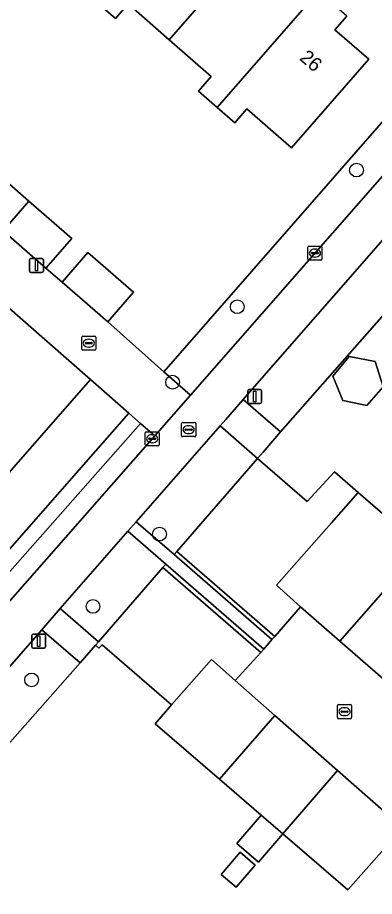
# Model space of a CAD drawing. Extents: x 158472 to 159562, y 388525 to 389606.
# Drawn here: x 158950 to 158975.4, y 388848.4 to 388910.9 of the extents above; entities that cross this region are included whole.
import ezdxf

# ---------------------------------------------------------------- set-up
doc = ezdxf.new("R2010")
doc.units = 0
for name, color, linetype in [('IMGEO_Berm_groen', 7, 'Continuous'), ('IMGEO_Boom', 7, 'Continuous'), ('IMGEO_Erf', 7, 'Continuous'), ('IMGEO_Fietspad_gesloten', 7, 'Continuous'), ('IMGEO_Groenvoorziening', 7, 'Continuous'), ('IMGEO_Kolk', 7, 'Continuous'), ('IMGEO_Lichtmast', 7, 'Continuous'), ('IMGEO_Muur', 7, 'Continuous'), ('IMGEO_Pand', 7, 'Continuous'), ('IMGEO_Pand_nummerreeks', 7, 'Continuous'), ('IMGEO_Rijbaan_lokaal_open', 7, 'Continuous'), ('IMGEO_Rioolput', 7, 'Continuous'), ('IMGEO_Voetpad_open', 7, 'Continuous')]:
    doc.layers.add(name, color=color, linetype=linetype)

msp = doc.modelspace()

# ---------------------------------------------------------------- linework, layer by layer
at = {"layer": 'IMGEO_Berm_groen'}
for points in [[(158986.075, 388905.713), (158985.406, 388905.499), (158984.817, 388905.117), (158966.103, 388883.752), (158968.762, 388881.439), (158988.788, 388904.188)], [(158954.488, 388865.021), (158951.767, 388867.379), (158941.937, 388856.138), (158932.045, 388844.827)], [(158932.107, 388843.92), (158934.223, 388842.084), (158954.488, 388865.021)]]:
    msp.add_lwpolyline(points, dxfattribs=at)
for points in [[(158967.11, 388879.563), (158964.456, 388881.871), (158958.484, 388875.052), (158961.177, 388872.718), (158961.375, 388872.943)], [(158960.386, 388871.802), (158960.59, 388872.036), (158957.887, 388874.378), (158953.083, 388868.884), (158955.81, 388866.522)]]:
    msp.add_lwpolyline(points, close=True, dxfattribs=at)
at = {"layer": 'IMGEO_Boom'}
for centre in [(158974.162, 388900.065), (158965.679, 388890.348), (158961.072, 388884.979), (158960.143, 388874.179), (158955.41, 388869.039), (158951.045, 388863.807)]:
    msp.add_circle(centre, 0.489, dxfattribs=at)
at = {"layer": 'IMGEO_Erf'}
for points in [[(158916.349, 388912.847), (158912.713, 388908.701), (158917.24, 388904.733), (158921.825, 388900.714), (158924.012, 388898.797), (158926.241, 388896.842), (158922.576, 388892.663), (158927.12, 388888.678), (158929.463, 388886.623), (158930.515, 388887.823), (158932.528, 388887.999), (158933.736, 388886.94), (158935.906, 388885.038), (158940.415, 388881.084), (158938.432, 388878.823), (158940.675, 388876.856), (158943.023, 388874.797), (158945.014, 388877.068), (158946.766, 388875.531), (158955.225, 388885.178), (158933.436, 388904.261), (158929.786, 388907.457), (158928.836, 388908.759), (158918.298, 388933.043)], [(158928.728, 388923.855), (158935.982, 388907.162), (158945.799, 388898.553), (158947.637, 388900.659), (158950.849, 388897.857), (158953.895, 388895.199), (158952.057, 388893.093), (158953.206, 388892.096), (158955.047, 388894.211), (158958.302, 388891.378), (158956.461, 388889.263), (158960.457, 388885.716), (158982.198, 388910.573), (158963.265, 388927.1)], [(158973.473, 388911.017), (158972.628, 388910.046), (158975.03, 388907.954), (158969.541, 388901.65), (158966.363, 388904.418), (158965.499, 388903.426), (158964.255, 388904.51), (158962.923, 388905.67), (158963.83, 388906.713), (158960.832, 388909.324), (158957.901, 388911.876), (158957, 388910.841), (158955.599, 388912.061)], [(158977.456, 388853.29), (158973.547, 388848.892), (158968.923, 388852.867), (158967.178, 388850.853), (158965.638, 388852.177), (158967.382, 388854.192), (158964.404, 388856.752), (158959.822, 388860.691), (158960.987, 388862.036), (158956.052, 388866.312), (158955.835, 388866.062), (158955.593, 388866.271), (158954.488, 388865.021), (158934.223, 388842.084), (158935.951, 388840.584), (158962.949, 388817.149), (158977.95, 388834.432)]]:
    msp.add_lwpolyline(points, dxfattribs=at)
for points in [[(159014.649, 388873.584), (159009.7, 388879.13), (159009.691, 388881.445), (159000, 388891.989), (158988.788, 388904.188), (158968.762, 388881.439), (158967.507, 388880.013), (158967.11, 388879.563), (158970.648, 388876.486), (158972.587, 388878.607), (158974.289, 388877.137), (158978.812, 388873.23), (158976.909, 388871.042), (158981.434, 388867.108), (158983.016, 388868.906), (158984.505, 388867.595), (158982.931, 388865.806), (158985.959, 388863.173), (158990.479, 388859.243), (158992.082, 388857.849), (158995.085, 388855.237), (158999.05, 388855.408), (159000, 388856.515)], [(158976.064, 388884.655), (158974.887, 388883.313), (158973.195, 388883.687), (158972.474, 388885.408), (158973.645, 388886.806), (158975.487, 388886.444)], [(158961.177, 388872.718), (158968.144, 388866.68), (158968.34, 388866.907), (158961.375, 388872.943)], [(158960.386, 388871.802), (158967.351, 388865.766), (158967.554, 388866), (158960.59, 388872.036)], [(158964.528, 388849.984), (158965.878, 388851.554), (158966.948, 388850.635), (158965.598, 388849.064)]]:
    msp.add_lwpolyline(points, close=True, dxfattribs=at)
at = {"layer": 'IMGEO_Fietspad_gesloten'}
for points in [[(158982.556, 388907.1), (158962.346, 388884.059), (158959.807, 388881.165), (158941.286, 388860.117), (158939.547, 388858.13), (158926.586, 388843.327)], [(158932.045, 388844.827), (158941.937, 388856.138), (158951.767, 388867.379), (158953.083, 388868.884), (158957.887, 388874.378), (158958.484, 388875.052), (158964.456, 388881.871), (158964.852, 388882.323), (158966.103, 388883.752), (158984.817, 388905.117)]]:
    msp.add_lwpolyline(points, dxfattribs=at)
at = {"layer": 'IMGEO_Groenvoorziening'}
msp.add_lwpolyline([(158940.228, 388861.047), (158958.799, 388882.048), (158957.965, 388882.778), (158949.482, 388873.138), (158945.42, 388868.506), (158939.514, 388861.675)], close=True, dxfattribs=at)
at = {"layer": 'IMGEO_Kolk'}
for p, q in [((158970.777, 388894.66), (158971.629, 388894.66)), ((158970.702, 388893.734), (158970.702, 388894.586)), ((158970.961, 388894.154), (158970.961, 388894.166)), ((158971.399, 388894.117), (158971.001, 388894.117)), ((158971.004, 388894.203), (158971.402, 388894.203)), ((158971.19, 388894.44), (158971.215, 388894.44)), ((158971.445, 388894.166), (158971.445, 388894.154)), ((158971.703, 388894.586), (158971.703, 388893.734)), ((158971.629, 388893.66), (158970.777, 388893.66)), ((158971.213, 388893.88), (158971.188, 388893.88)), ((158954.615, 388887.328), (158954.615, 388888.18)), ((158954.69, 388888.254), (158955.542, 388888.254)), ((158954.874, 388887.748), (158954.874, 388887.76)), ((158954.917, 388887.797), (158955.315, 388887.797)), ((158955.103, 388888.034), (158955.128, 388888.034)), ((158955.358, 388887.76), (158955.358, 388887.748)), ((158955.616, 388888.18), (158955.616, 388887.328)), ((158955.542, 388887.254), (158954.69, 388887.254)), ((158955.312, 388887.711), (158954.914, 388887.711)), ((158955.126, 388887.474), (158955.101, 388887.474)), ((158959.122, 388880.532), (158959.122, 388881.384)), ((158959.197, 388881.458), (158960.049, 388881.458)), ((158959.381, 388880.952), (158959.381, 388880.964)), ((158959.819, 388880.915), (158959.421, 388880.915)), ((158959.424, 388881.001), (158959.822, 388881.001)), ((158959.61, 388881.238), (158959.635, 388881.238)), ((158959.865, 388880.964), (158959.865, 388880.952)), ((158960.123, 388881.384), (158960.123, 388880.532)), ((158960.049, 388880.458), (158959.197, 388880.458)), ((158959.633, 388880.678), (158959.608, 388880.678)), ((158972.809, 388861.127), (158972.809, 388861.979)), ((158972.884, 388862.053), (158973.736, 388862.053)), ((158973.068, 388861.547), (158973.068, 388861.559)), ((158973.506, 388861.51), (158973.108, 388861.51)), ((158973.111, 388861.596), (158973.509, 388861.596)), ((158973.297, 388861.833), (158973.322, 388861.833)), ((158973.552, 388861.559), (158973.552, 388861.547)), ((158973.81, 388861.979), (158973.81, 388861.127)), ((158973.736, 388861.053), (158972.884, 388861.053)), ((158973.32, 388861.273), (158973.295, 388861.273))]:
    msp.add_line(p, q, dxfattribs=at)
for points in [[(158970.777, 388894.66), (158971.629, 388894.66)], [(158970.702, 388893.734), (158970.702, 388894.586)], [(158971.703, 388894.586), (158971.703, 388893.734)], [(158971.629, 388893.66), (158970.777, 388893.66)], [(158954.615, 388887.328), (158954.615, 388888.18)], [(158954.69, 388888.254), (158955.542, 388888.254)], [(158955.616, 388888.18), (158955.616, 388887.328)], [(158955.542, 388887.254), (158954.69, 388887.254)], [(158959.122, 388880.532), (158959.122, 388881.384)], [(158959.197, 388881.458), (158960.049, 388881.458)], [(158960.123, 388881.384), (158960.123, 388880.532)], [(158960.049, 388880.458), (158959.197, 388880.458)], [(158972.809, 388861.127), (158972.809, 388861.979)], [(158972.884, 388862.053), (158973.736, 388862.053)], [(158973.81, 388861.979), (158973.81, 388861.127)], [(158973.736, 388861.053), (158972.884, 388861.053)]]:
    msp.add_lwpolyline(points, dxfattribs=at)
for centre, radius, start, end in [((158970.779, 388894.584), 0.0765, 91.55205, 178.44795), ((158970.779, 388894.584), 0.0765, 91.55205, 178.44795), ((158971.627, 388894.584), 0.0765, 1.55205, 88.44795), ((158971.627, 388894.584), 0.0765, 1.55205, 88.44795), ((158971.001, 388894.163), 0.0403, 85.87752, 175.75265), ((158970.998, 388894.153), 0.0366, 178.93798, 274.71019), ((158971.402, 388894.16), 0.043, 264.86636, 352.45326), ((158971.406, 388894.165), 0.0386, 1.73085, 96.63898), ((158970.779, 388893.736), 0.0765, 181.55205, 268.44795), ((158970.779, 388893.736), 0.0765, 181.55205, 268.44795), ((158971.627, 388893.736), 0.0765, 271.55205, 358.44795), ((158971.627, 388893.736), 0.0765, 271.55205, 358.44795), ((158954.692, 388888.178), 0.0765, 91.55205, 178.44795), ((158954.692, 388888.178), 0.0765, 91.55205, 178.44795), ((158954.914, 388887.757), 0.0403, 85.87752, 175.75265), ((158954.911, 388887.747), 0.0366, 178.93798, 274.71019), ((158955.315, 388887.754), 0.043, 264.86636, 352.45326), ((158955.319, 388887.759), 0.0386, 1.73085, 96.63898), ((158955.54, 388888.178), 0.0765, 1.55205, 88.44795), ((158955.54, 388888.178), 0.0765, 1.55205, 88.44795), ((158954.692, 388887.33), 0.0765, 181.55205, 268.44795), ((158954.692, 388887.33), 0.0765, 181.55205, 268.44795), ((158955.54, 388887.33), 0.0765, 271.55205, 358.44795), ((158955.54, 388887.33), 0.0765, 271.55205, 358.44795), ((158959.199, 388881.382), 0.0765, 91.55205, 178.44795), ((158959.199, 388881.382), 0.0765, 91.55205, 178.44795), ((158959.421, 388880.961), 0.0403, 85.87752, 175.75265), ((158959.418, 388880.951), 0.0366, 178.93798, 274.71019), ((158959.822, 388880.958), 0.043, 264.86636, 352.45326), ((158959.826, 388880.963), 0.0386, 1.73085, 96.63898), ((158960.047, 388881.382), 0.0765, 1.55205, 88.44795), ((158960.047, 388881.382), 0.0765, 1.55205, 88.44795), ((158959.199, 388880.534), 0.0765, 181.55205, 268.44795), ((158959.199, 388880.534), 0.0765, 181.55205, 268.44795), ((158960.047, 388880.534), 0.0765, 271.55205, 358.44795), ((158960.047, 388880.534), 0.0765, 271.55205, 358.44795), ((158972.886, 388861.977), 0.0765, 91.55205, 178.44795), ((158972.886, 388861.977), 0.0765, 91.55205, 178.44795), ((158973.108, 388861.556), 0.0403, 85.87752, 175.75265), ((158973.105, 388861.546), 0.0366, 178.93798, 274.71019), ((158973.509, 388861.553), 0.043, 264.86636, 352.45326), ((158973.513, 388861.558), 0.0386, 1.73085, 96.63898), ((158973.734, 388861.977), 0.0765, 1.55205, 88.44795), ((158973.734, 388861.977), 0.0765, 1.55205, 88.44795), ((158972.886, 388861.129), 0.0765, 181.55205, 268.44795), ((158972.886, 388861.129), 0.0765, 181.55205, 268.44795), ((158973.734, 388861.129), 0.0765, 271.55205, 358.44795), ((158973.734, 388861.129), 0.0765, 271.55205, 358.44795)]:
    msp.add_arc(centre, radius, start, end, dxfattribs=at)
for centre, major_axis, ratio, start_param, end_param in [((158971.189, 388894.16), (-0.387, 0.002), 0.722429, 4.712389, 7.853982), ((158971.214, 388894.16), (-0.39, 0.002), 0.717154, 1.570796, 4.712389), ((158955.102, 388887.754), (-0.387, 0.002), 0.722429, 4.712389, 7.853982), ((158955.127, 388887.754), (-0.39, 0.002), 0.717154, 1.570796, 4.712389), ((158959.609, 388880.958), (-0.387, 0.002), 0.722429, 4.712389, 7.853982), ((158959.634, 388880.958), (-0.39, 0.002), 0.717154, 1.570796, 4.712389), ((158973.296, 388861.553), (-0.387, 0.002), 0.722429, 4.712389, 7.853982), ((158973.321, 388861.553), (-0.39, 0.002), 0.717154, 1.570796, 4.712389)]:
    msp.add_ellipse(centre, major_axis=major_axis, ratio=ratio, start_param=start_param, end_param=end_param, dxfattribs=at)
at = {"layer": 'IMGEO_Lichtmast'}
for p, q in [((158950.89, 388892.884), (158950.89, 388893.684)), ((158950.89, 388893.684), (158950.89, 388892.884)), ((158950.99, 388893.784), (158951.78, 388893.784)), ((158951.78, 388893.784), (158950.99, 388893.784)), ((158951.88, 388893.684), (158951.88, 388892.884)), ((158951.88, 388892.884), (158951.88, 388893.684)), ((158951.78, 388892.784), (158950.99, 388892.784)), ((158950.99, 388892.784), (158951.78, 388892.784)), ((158966.419, 388883.561), (158966.419, 388884.361)), ((158966.419, 388884.361), (158966.419, 388883.561)), ((158966.519, 388884.461), (158967.309, 388884.461)), ((158967.309, 388884.461), (158966.519, 388884.461)), ((158967.409, 388884.361), (158967.409, 388883.561)), ((158967.409, 388883.561), (158967.409, 388884.361)), ((158967.309, 388883.461), (158966.519, 388883.461)), ((158966.519, 388883.461), (158967.309, 388883.461)), ((158951.047, 388866.158), (158951.047, 388866.958)), ((158951.047, 388866.958), (158951.047, 388866.158)), ((158951.147, 388867.058), (158951.937, 388867.058)), ((158951.937, 388867.058), (158951.147, 388867.058)), ((158952.037, 388866.958), (158952.037, 388866.158)), ((158952.037, 388866.158), (158952.037, 388866.958)), ((158951.937, 388866.058), (158951.147, 388866.058)), ((158951.147, 388866.058), (158951.937, 388866.058))]:
    msp.add_line(p, q, dxfattribs=at)
for points in [[(158951.31, 388893.659), (158951.46, 388893.659), (158951.46, 388892.909), (158951.31, 388892.909), (158951.31, 388893.659)], [(158966.839, 388884.336), (158966.989, 388884.336), (158966.989, 388883.586), (158966.839, 388883.586), (158966.839, 388884.336)], [(158951.467, 388866.933), (158951.617, 388866.933), (158951.617, 388866.183), (158951.467, 388866.183), (158951.467, 388866.933)]]:
    msp.add_lwpolyline(points, dxfattribs=at)
for centre, start, end in [((158950.99, 388893.684), 90, 180), ((158950.99, 388893.684), 90, 180), ((158951.78, 388893.684), 0, 90), ((158951.78, 388893.684), 360, 90), ((158950.99, 388892.884), 180, 270), ((158950.99, 388892.884), 180, 270), ((158951.78, 388892.884), 270, 0), ((158951.78, 388892.884), 270, 0), ((158966.519, 388884.361), 90, 180), ((158966.519, 388884.361), 90, 180), ((158967.309, 388884.361), 0, 90), ((158967.309, 388884.361), 360, 90), ((158966.519, 388883.561), 180, 270), ((158966.519, 388883.561), 180, 270), ((158967.309, 388883.561), 270, 0), ((158967.309, 388883.561), 270, 0), ((158951.147, 388866.958), 90, 180), ((158951.147, 388866.958), 90, 180), ((158951.937, 388866.958), 0, 90), ((158951.937, 388866.958), 360, 90), ((158951.147, 388866.158), 180, 270), ((158951.147, 388866.158), 180, 270), ((158951.937, 388866.158), 270, 0), ((158951.937, 388866.158), 270, 0)]:
    msp.add_arc(centre, 0.1, start, end, dxfattribs=at)
at = {"layer": 'IMGEO_Muur'}
msp.add_lwpolyline([(158955.225, 388885.178), (158933.436, 388904.261)], dxfattribs=at)
at = {"layer": 'IMGEO_Pand'}
for points in [[(158955.599, 388912.061), (158957, 388910.841), (158957.901, 388911.876), (158960.832, 388909.324), (158966.287, 388915.59), (158964.012, 388917.571), (158964.85, 388918.533), (158962.793, 388920.325)], [(158964.255, 388904.51), (158971.452, 388912.777), (158969.405, 388914.56), (158968.57, 388913.601), (158966.287, 388915.59), (158960.832, 388909.324), (158963.83, 388906.713), (158962.923, 388905.67)], [(158964.255, 388904.51), (158965.499, 388903.426), (158966.363, 388904.418), (158969.541, 388901.65), (158975.03, 388907.954), (158972.628, 388910.046), (158973.473, 388911.017), (158971.452, 388912.777)], [(158949.013, 388895.748), (158950.849, 388897.857), (158947.637, 388900.659), (158945.799, 388898.553)], [(158949.013, 388895.748), (158952.057, 388893.093), (158953.895, 388895.199), (158950.849, 388897.857)], [(158956.461, 388889.263), (158958.302, 388891.378), (158955.047, 388894.211), (158953.206, 388892.096)], [(158975.487, 388886.444), (158973.645, 388886.806), (158972.474, 388885.408), (158973.195, 388883.687), (158974.887, 388883.313), (158976.064, 388884.655)], [(158940.675, 388876.856), (158934.659, 388869.969), (158939.343, 388865.862), (158943.295, 388870.369), (158945.42, 388868.506), (158949.482, 388873.138), (158957.965, 388882.778), (158955.225, 388885.178), (158946.766, 388875.531), (158945.014, 388877.068), (158943.023, 388874.797)], [(158972.384, 388874.977), (158974.289, 388877.137), (158972.587, 388878.607), (158970.648, 388876.486), (158967.11, 388879.563), (158961.375, 388872.943), (158968.34, 388866.907), (158970.168, 388869.017), (158968.47, 388870.54)], [(158976.909, 388871.042), (158978.812, 388873.23), (158974.289, 388877.137), (158972.384, 388874.977), (158968.47, 388870.54), (158970.168, 388869.017), (158972.973, 388866.57)], [(158967.351, 388865.766), (158960.386, 388871.802), (158955.81, 388866.522), (158955.593, 388866.271), (158955.835, 388866.062), (158956.052, 388866.312), (158960.987, 388862.036), (158963.85, 388865.25), (158965.535, 388863.766)], [(158976.909, 388871.042), (158972.973, 388866.57), (158977.492, 388862.628), (158981.434, 388867.108)], [(158964.404, 388856.752), (158968.353, 388861.289), (158965.535, 388863.766), (158963.85, 388865.25), (158960.987, 388862.036), (158959.822, 388860.691)], [(158972.819, 388857.365), (158968.353, 388861.289), (158964.404, 388856.752), (158967.382, 388854.192), (158968.923, 388852.867)], [(158968.923, 388852.867), (158973.547, 388848.892), (158977.456, 388853.29), (158972.819, 388857.365)], [(158968.923, 388852.867), (158967.382, 388854.192), (158965.638, 388852.177), (158967.178, 388850.853)], [(158964.528, 388849.984), (158965.598, 388849.064), (158966.948, 388850.635), (158965.878, 388851.554)]]:
    msp.add_lwpolyline(points, close=True, dxfattribs=at)
at = {"layer": 'IMGEO_Rijbaan_lokaal_open'}
msp.add_lwpolyline([(158977.492, 388862.628), (158972.973, 388866.57), (158970.168, 388869.017), (158968.34, 388866.907), (158968.144, 388866.68), (158967.554, 388866), (158967.351, 388865.766), (158965.535, 388863.766), (158968.353, 388861.289), (158972.819, 388857.365), (158977.456, 388853.29)], dxfattribs=at)
at = {"layer": 'IMGEO_Rioolput'}
for p, q in [((158961.792, 388882.107), (158962.644, 388882.107)), ((158961.717, 388881.181), (158961.717, 388882.033)), ((158961.976, 388881.601), (158961.976, 388881.613)), ((158962.414, 388881.564), (158962.016, 388881.564)), ((158962.019, 388881.65), (158962.417, 388881.65)), ((158962.205, 388881.887), (158962.23, 388881.887)), ((158962.46, 388881.613), (158962.46, 388881.601)), ((158962.718, 388882.033), (158962.718, 388881.181)), ((158962.644, 388881.107), (158961.792, 388881.107)), ((158962.228, 388881.327), (158962.203, 388881.327))]:
    msp.add_line(p, q, dxfattribs=at)
for points in [[(158961.792, 388882.107), (158962.644, 388882.107)], [(158961.717, 388881.181), (158961.717, 388882.033)], [(158962.718, 388882.033), (158962.718, 388881.181)], [(158962.644, 388881.107), (158961.792, 388881.107)]]:
    msp.add_lwpolyline(points, dxfattribs=at)
for centre, radius, start, end in [((158961.794, 388882.031), 0.0765, 91.55205, 178.44795), ((158961.794, 388882.031), 0.0765, 91.55205, 178.44795), ((158962.642, 388882.031), 0.0765, 1.55205, 88.44795), ((158962.642, 388882.031), 0.0765, 1.55205, 88.44795), ((158962.016, 388881.61), 0.0403, 85.87752, 175.75265), ((158962.013, 388881.6), 0.0366, 178.93798, 274.71019), ((158962.417, 388881.607), 0.043, 264.86636, 352.45326), ((158962.421, 388881.612), 0.0386, 1.73085, 96.63898), ((158961.794, 388881.183), 0.0765, 181.55205, 268.44795), ((158961.794, 388881.183), 0.0765, 181.55205, 268.44795), ((158962.642, 388881.183), 0.0765, 271.55205, 358.44795), ((158962.642, 388881.183), 0.0765, 271.55205, 358.44795)]:
    msp.add_arc(centre, radius, start, end, dxfattribs=at)
for centre, major_axis, ratio, start_param, end_param in [((158962.204, 388881.607), (-0.387, 0.002), 0.722429, 4.712389, 7.853982), ((158962.229, 388881.607), (-0.39, 0.002), 0.717154, 1.570796, 4.712389)]:
    msp.add_ellipse(centre, major_axis=major_axis, ratio=ratio, start_param=start_param, end_param=end_param, dxfattribs=at)
at = {"layer": 'IMGEO_Voetpad_open'}
msp.add_lwpolyline([(158983.711, 388912.434), (158982.198, 388910.573), (158960.457, 388885.716), (158962.346, 388884.059), (158982.556, 388907.1), (158984.126, 388908.89), (158991.035, 388916.747)], dxfattribs=at)
for points in [[(158953.206, 388892.096), (158952.057, 388893.093), (158949.013, 388895.748), (158945.799, 388898.553), (158935.982, 388907.162), (158933.436, 388904.261), (158955.225, 388885.178), (158957.965, 388882.778), (158958.799, 388882.048), (158959.807, 388881.165), (158962.346, 388884.059), (158960.457, 388885.716), (158956.461, 388889.263)], [(158966.103, 388883.752), (158964.852, 388882.323), (158964.456, 388881.871), (158967.11, 388879.563), (158967.507, 388880.013), (158968.762, 388881.439)], [(158938.477, 388859.066), (158938.627, 388858.934), (158939.547, 388858.13), (158941.286, 388860.117), (158959.807, 388881.165), (158958.799, 388882.048), (158940.228, 388861.047)], [(158958.484, 388875.052), (158957.887, 388874.378), (158960.59, 388872.036), (158967.554, 388866), (158968.144, 388866.68), (158961.177, 388872.718)], [(158953.083, 388868.884), (158951.767, 388867.379), (158954.488, 388865.021), (158955.593, 388866.271), (158955.81, 388866.522)]]:
    msp.add_lwpolyline(points, close=True, dxfattribs=at)

# ---------------------------------------------------------------- texts
at = {"layer": 'IMGEO_Pand_nummerreeks'}
msp.add_text('26', height=1, rotation=318.94606, dxfattribs=at).set_placement((158970.041, 388907.949))

doc.saveas('drawing.dxf')
